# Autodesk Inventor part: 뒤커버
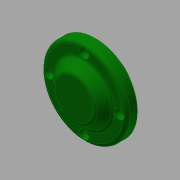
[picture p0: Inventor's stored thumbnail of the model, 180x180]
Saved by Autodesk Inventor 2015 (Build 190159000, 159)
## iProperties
Created: 2017-08
Part Number: 뒤커버
Material: 알루미늄 6061
Document SubType Name: Modeling
Designer: mduedu
Density: 2.71 g/cm^3
Appearance: 진녹색
Mass: 112.306 g
Surface Area: 136.493 cm^2
Volume: 41.4412 cm^3
Author: mduedu
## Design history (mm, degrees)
sketch "스케치1"
  geometry: C1 r 35 at (0, 0); 1 further point
  constraints: 1 centre point, 1 coincident
  dimensions: "d0" = 70 diameter of C1
extrude "돌출1" new body sketch "스케치1" distance "d1" = 10; taper "d2" = 0 deg
sketch "스케치2"
  geometry: C1 r 24 at (0, 0); 1 further point
  constraints: 1 centre point, 1 coincident
  dimensions: "d3" = 48 diameter of C1
node "작업 평면1"
sketch "스케치3"
  geometry: C1 r 17 at (0, 0); 1 further point
  constraints: 1 centre point, 1 coincident
  dimensions: "d5" = 34 diameter of C1
feature "로프트1" sketch "스케치3" dims "d6" = 0, "d7" = 90 deg, "d8" = 0, "d9" = 90 deg
sketch "스케치4"
  geometry: C1 r 24 at (0, 0) reference; 1 further point
extrude "돌출2" join sketch "스케치4" distance "d10" = 8; taper "d11" = 0 deg
hole "구멍1" diameter "d14" = 40; stored, may be unused: countersink angle "d18" = 90 deg, drill point angle "d20" = 0 deg; dims "d12" = 10, "d13" = 10, "d15" = 6, "d16" = 4, "d17" = 2, "d19" = 12
hole "구멍2" diameter "d23" = 34; stored, may be unused: countersink angle "d27" = 90 deg, drill point angle "d29" = 0 deg; dims "d24" = 6, "d25" = 4, "d26" = 2, "d28" = 6, "d62" = 10, "d63" = 10
chamfer "모따기1" distance "d39" = 1; stored, may be unused: second distance "d40" = 2, angle "d41" = 45 deg
fillet "모깎기1" dims "d42" = 0.3
fillet "모깎기2" dims "d43" = 3
sketch "스케치5" dims "d44" = 58
  geometry: 6 further points
  constraints: 2 vertical alignment, 1 coincident, 7 other
  dimensions: "d47" = 360 deg dimension on point (0, 0) point (0, 29) (derived)
sketch "스케치6"
  geometry: 4 further points
  constraints: 4 other
hole "구멍4" sketch "스케치6" at (0, 29), (-29, 0), (29, 0), (0, -29) diameter "d49" = 4.5; stored, may be unused: countersink angle "d53" = 90 deg, drill point angle "d55" = 0 deg; dims "d50" = 6, "d51" = 8, "d52" = 4.6, "d54" = 8
fillet "모깎기3" dims "d56" = 3
fillet "모깎기4" dims "d57" = 3
fillet "모깎기5" dims "d58" = 3
chamfer "모따기2" distance "d59" = 1; stored, may be unused: second distance "d60" = 2, angle "d61" = 45 deg
node "솔리드1"
other parameters: "d4" = 8
